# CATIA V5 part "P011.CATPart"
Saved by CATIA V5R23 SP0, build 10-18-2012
Part number: P011
Definition: Flasque arrière
Bounding box of the stored display mesh (mm): x -62 to -28, y -80 to 80, z -79.951 to 79.951
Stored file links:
  C:\wamp\www\COURS\CONCEPTION GMP1\TITRE 02-SEMESTRE 2\03-TP7-PRESSE MECANIQUE\eleve\P011.CATPart
  C:\Documents and Settings\Samuel\Mes documents\Cours\Projet Tutoret\Licence Pro - Presse\Presse\Presse mecanique.CATProduct
  C:\Documents and Settings\Samuel\Mes documents\Cours\Projet Tutoret\Licence Pro - Presse\Presse\bati_droit.CATPart
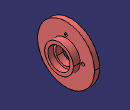
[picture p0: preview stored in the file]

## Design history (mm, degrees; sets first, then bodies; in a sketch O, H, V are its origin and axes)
Body1 (main body)
  Sketch1 on yz-plane, origin (0, 0, 0), H (0, 1, 0), V (0, 0, 1)
    circle A1 centre (0, 0) radius 40
    radius A1 = 40
  Pad1: profile Sketch1, direction (-1, 0, 0), length 48, opposite side length -28
  Sketch2 on face of Pad1, origin (-48, 0, 0), H (0, -1, 0), V (0, 0, 1)
    circle A1 centre (0, 0) radius 80
    radius A1 = 80
  Pad2: profile Sketch2, direction (-1, 0, 0), length 14
  Sketch3 on face of Pad2, origin (-62, 0, 0), H (0, 1, 0), V (0, 0, -1)
    point P1 (0, 0)
  Hole1: placed by Sketch3, at (-62, 0, 0) direction (1, 0, 0), diameter 50, through (limit type 3)
  Sketch4 on face of Pad1, origin (-28, 0, 0), H (0, 1, 0), V (0, 0, 1)
    point P1 (0, 0)
  Hole2: placed by Sketch4, at (-28, 0, 0) direction (-1, 0, 0), diameter 62, depth 16
  Sketch5 on face of Pad2, origin (-62, 0, 0), H (0, 1, 0), V (0, 0, -1)
    point P1 (0, 48)
    reference intersected line E1 through (0, 0) direction (0, 1) from zx-plane
    reference intersected line E2 through (0, 0) direction (1, 0) from xy-plane
    distance E2 P1 = 48
    coincidence: E1 P1
  Hole3: placed by Sketch5, at (-62, 0, -48) direction (1, 0, 0), diameter 8.5, through (limit type 6), counterbore diameter 13, counterbore depth 7
  CircPattern1: of Hole3, instances 4, angular step 90, axis from face of Pad2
